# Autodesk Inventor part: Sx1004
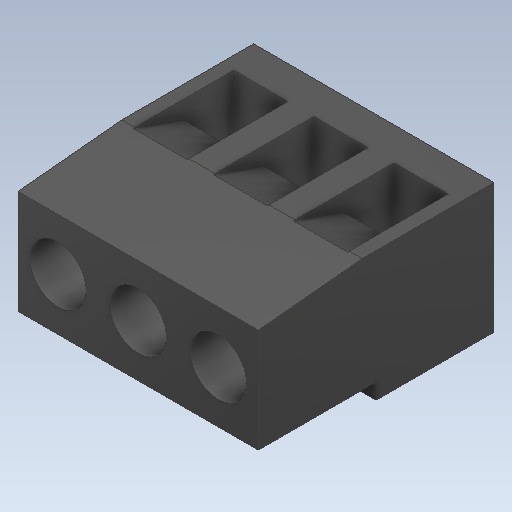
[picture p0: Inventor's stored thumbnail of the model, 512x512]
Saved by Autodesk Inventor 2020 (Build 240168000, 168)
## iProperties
Created: 2021-02
Part Number: Sx1004
Material: Generico
Document SubType Name: Modeling
Designer: zambolin
Density: 1 g/cm^3
Appearance: Default
Author: zambolin
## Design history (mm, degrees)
feature "Solido2"
node "Solido1"
